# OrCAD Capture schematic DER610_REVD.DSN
size B; title: DER 610 - 5V 2A; rev: B
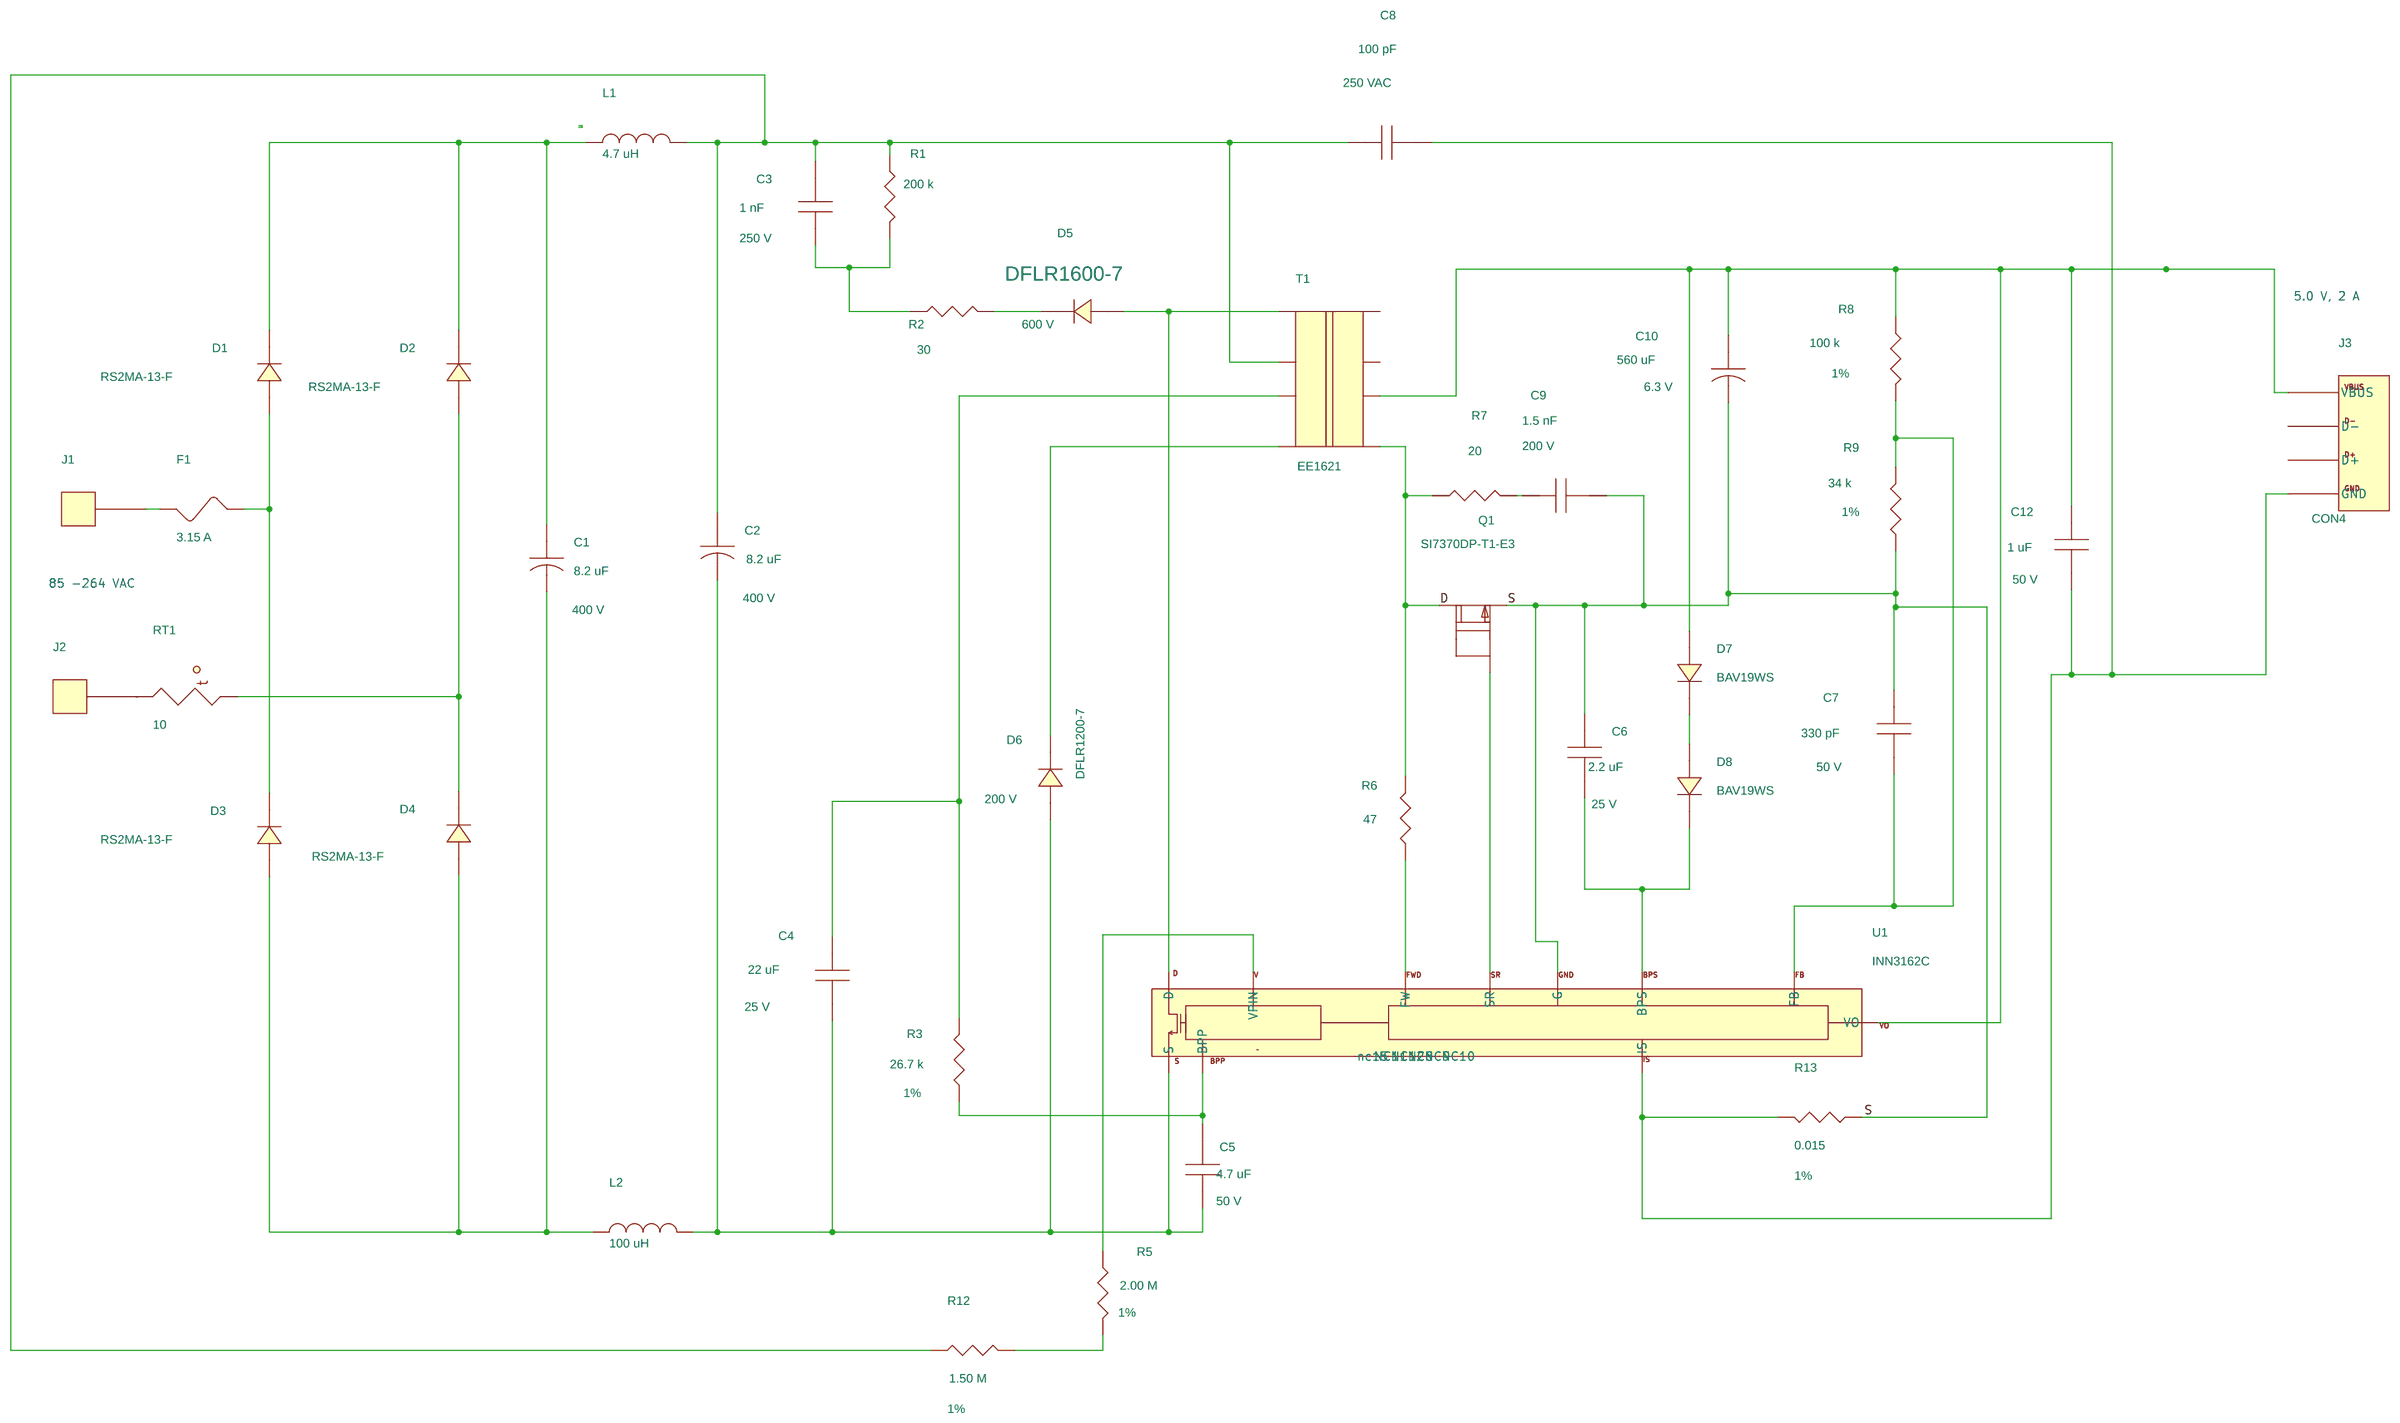
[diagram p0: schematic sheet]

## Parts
C1  8.2 uF  [pipolcapclyd320ls140030]
C2  8.2 uF  [pipolcapclyd320ls140030]
C3  1 nF  [pismc0805]
C4  22 uF  [pismc0805]
C5  4.7 uF  [pismc0805]
C6  2.2 uF  [pismc0805]
C7  330 pF  [pismc0603]
C8  100 pF  [pinpycaprad500x220ls400040]
C9  1.5 nF  [pismc0805]
C10  560 uF  [pi_polcap_d248ls098d035]
C12  1 uF  [pismc0805]
D1  RS2MA-13-F  [pismdo214ac12]
D2  RS2MA-13-F  [pismdo214ac12]
D3  RS2MA-13-F  [pismdo214ac12]
D4  RS2MA-13-F  [pismdo214ac12]
D5  DFLR1600-7  [pismddflr120012]
D6  DFLR1200-7  [pismddflr120012]
D7  BAV19WS  [pismsod323]
D8  BAV19WS  [pismsod323]
F1  3.15 A  [pi_rst_microfuse]
J1  PCB Terminal 30 AWG  [pi_hole_30awg]
J2  PCB Terminal 30 AWG  [pi_hole_30awg]
J3  CON4  [pi_usb_4p_GoldConn]
L1  4.7 uH  [pismr0805]
L2  100 uH  [pi_choke_365hx275ls118d030]
Q1  SI7370DP-T1-E3  [pismpqfn5x6b]
R1  200 k  [pismr0805]
R2  30  [pismr0805]
R3  26.7 k  [pismr0603]
R5  2.00 M  [pismr1206]
R6  47  [pismr0603]
R7  20  [pismr0805]
R8  100 k  [pismr0603]
R9  34 k  [pismr0603]
R12  1.50 M  [pismr1206]
R13  0.015  [pismr0805]
RT1  10  [pi_rad_276DX197T_ls100d025]
T1  EE1621  [pi_bobbin_ee1621_8p]
U1  INN3162C  [pi_ic_insop_24d]

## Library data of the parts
C1 C2 = CAP_POL: ALT_SYMBOLS: pipolcapclyd320ls140030575h; Disp_Voltage: 400 V; FPLIST: pipolcapclyd320ls140030,pipolcapclyd320ls140030575h; Part Number: 20-08724-00; Voltage: 400 V
C3 = CAP_NP: Disp_Voltage: 250 V; Part Number: 20-00736-00; Voltage: 250 V
C4 = CAP_NP: Disp_Voltage: 25 V; Part Number: 20-08746-00; Voltage: 25 V
C5 = CAP_NP: Disp_Voltage: 50 V; Part Number: 20-01130-00; Voltage: 50 V
C6 = CAP_NP: Disp_Voltage: 25 V; Part Number: 20-08603-00; Voltage: 25 V
C7 = CAP_NP: Disp_Voltage: 50 V; Part Number: 20-08676-00; Voltage: 50 V
C8 = CAP_NP: Disp_Voltage: 250 VAC; Part Number: 20-00403-00; Voltage: 250 VAC
C9 = CAP_NP: Disp_Voltage: 200 V; PCB Editor PCBFP: pismc0603; Part Number: 20-01150-00; Voltage: 200 V
C10 = CAP_POL: Disp_Voltage: 6.3 V; Part Number: 20-08672-00; Voltage: 6.3 V
C12 = CAP_NP: Disp_Voltage: 50 V; Part Number: 20-00853-00; Voltage: 50 V
D1-D4 = DIODE: Part Number: 15-01059-00
D5 = DIODE: Disp_Voltage: 600 V; Part Number: 15-00826-00
D6 = DIODE: Disp_Voltage: 200 V; Part Number: 15-01019-00
D7 D8 = DIODE: Part Number: 15-00658-00
F1 = FUSE: ALT_SYMBOLS: pirstmicrofusehoz; FPLIST: pi_rst_microfuse,pirstmicrofusehoz; Part Number: 40-00020-00
J1 J2 = TERM_1Pin: Part Number: 35-00026-00
J3 = CON4_USB_1: Part Number: 35-00238-00
L1 = INDUCTOR: Part Number: 30-00372-00
L2 = INDUCTOR: Part Number: 30-00306-00
Q1 = FET_N_SGD_123_4_5678: Part Number: 50-00136-00
R1 = R: Part Number: 05-01574-00
R2 = R: Part Number: 05-01482-00
R3 = R: Disp_Tol: 1%; Part Number: 05-03225-00
R5 = R: Disp_Tol: 1%; Part Number: 05-03156-00
R6 = R: Part Number: 05-01656-00
R7 = R: Part Number: 05-01478-00
R8 = R: Disp_Tol: 1%; Part Number: 05-01174-00
R9 = R: Disp_Tol: 1%; Part Number: 05-03235-00
R12 = R: Disp_Tol: 1%; Part Number: 05-03153-00
R13 = R: Disp_Tol: 1%; Part Number: 05-06373-00
RT1 = THERMISTOR: Part Number: 90-00047-00
T1 = BEE16_8P_GENERIC: Part Number: 25-01044-00
U1 = DEV_Inno3CE: Part Number: 10-01029-00

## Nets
D: Q1.5(D) Q1.6(D) Q1.7(D) Q1.8(D) R6.1 R7.2 T1.5
NC8: U1.8(NC8)
NC9: U1.9(NC9)
NC10: U1.10(NC10)
NC11: U1.11(NC11)
NC12: U1.12(NC12)
NC15: U1.15(nc15)
S: C6.1 C7.1 C9.2 C10.2 Q1.1(S) Q1.2(S) Q1.3(S) R9.2 R13.2 U1.2(G)
N2609146: C2.1 C3.2 C8.1 L1.2 R1.2 R12.1 T1.2
N2609210: C1.1 D1.1 D2.1 L1.1
N2609274: C8.2 C12.2 J3.4(GND) R13.1 U1.1(IS)
N2609316: C3.1 R1.1 R2.2
N2609336: C10.1 C12.1 D7.2 J3.1(VBUS) R8.1 T1.6 U1.6(VO)
N2609430: D5.1 R2.1
N2609434: D5.2 T1.1 U1.24(D)
N2609584: C4.1 R3.1 T1.3
N2609600: D1.2 D3.1 F1.1
N2609604: D2.2 D4.1 RT1.2
N2609612: C7.2 R8.2 R9.1 U1.3(FB)
N2609632: D6.1 T1.4
N2609750: C9.1 R7.1
N2609770: F1.2 J1.1
N2609868: C2.2 C4.2 C5.1 D6.2 L2.2 U1.16(S)
N2609876: C1.2 D3.2 D4.2 L2.1
N2609984: Q1.4(G) U1.5(SR)
N2610014: J2.1 RT1.1
N2610090: C6.2 D8.1 U1.4(BPS)
N2610148: R6.2 U1.7(FW)
N2610260: C5.2 R3.2 U1.14(BPP)
N2616533: R5.1 U1.13(VPIN)
N2616648: R5.2 R12.2
N2624391: D7.1 D8.2

Not connected (* = marked no-connect by the designer): J3 2(D-) 3(D+); T1 7 8

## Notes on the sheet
- 5.0 V, 2 A
- 85 -264 VAC
